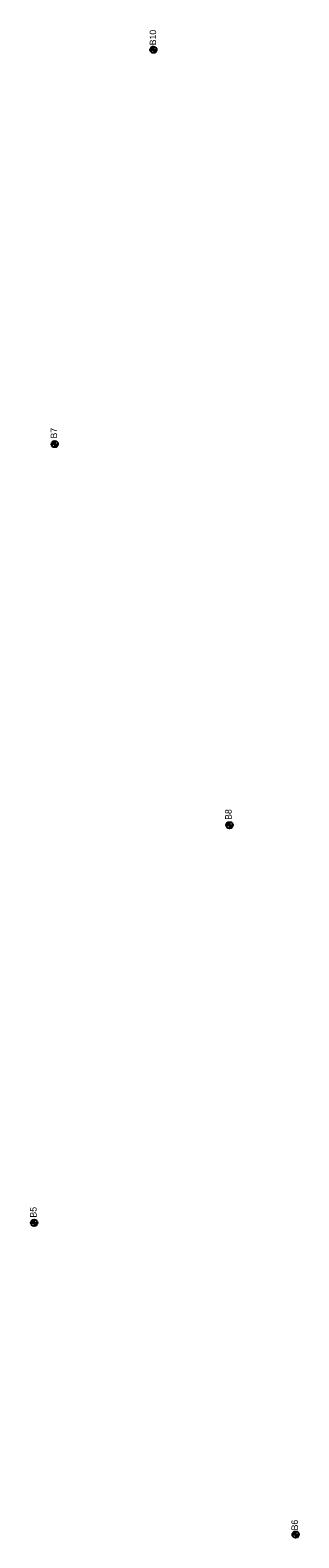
# Model space of a CAD drawing. Extents: x 327762 to 372792, y 127949 to 259367.
# Drawn here: x 361394 to 361809, y 130316 to 132638 of the extents above; entities that cross this region are included whole.
import ezdxf

# ---------------------------------------------------------------- set-up
doc = ezdxf.new("R2010")
doc.units = 0
for name, color, linetype in [('E_SOIL_BORE1 [KAPUR_CADDS_LEVELS]', 7, 'Continuous'), ('E_SOIL_BORE2 [KAPUR_CADDS_LEVELS]', 7, 'Continuous'), ('P_MARK', 7, 'Continuous')]:
    doc.layers.add(name, color=color, linetype=linetype)

msp = doc.modelspace()

# ---------------------------------------------------------------- linework, layer by layer
at = {"layer": 'P_MARK'}
for p, q in [((361584.5, 132612.5), (361584.5, 132602.5)), ((361579.5, 132607.5), (361589.5, 132607.5)), ((361427.2, 132000.1), (361437.2, 132000.1)), ((361432.2, 132005.1), (361432.2, 131995.1)), ((361697, 131413), (361707, 131413)), ((361702, 131418), (361702, 131408)), ((361395.5, 130800.6), (361405.5, 130800.6)), ((361400.5, 130805.6), (361400.5, 130795.6)), ((361799, 130320.5), (361809, 130320.5)), ((361804, 130325.5), (361804, 130315.5))]:
    msp.add_line(p, q, dxfattribs=at)
for centre in [(361584.5, 132607.5), (361432.2, 132000.1), (361702, 131413), (361400.5, 130800.6), (361804, 130320.5)]:
    msp.add_circle(centre, 5, dxfattribs=at)
for centre, radius, start, end in [((361584.5, 132607.5), 4.5, 89.9869, 179.9869), ((361584.5, 132607.5), 4, 89.9869, 179.9869), ((361584.5, 132607.5), 3.5, 89.9869, 179.9869), ((361584.5, 132607.5), 3, 89.9869, 179.9869), ((361584.5, 132607.5), 2.5, 89.9869, 179.9869), ((361584.5, 132607.5), 2, 89.9869, 179.9869), ((361584.5, 132607.5), 1.5, 89.9869, 179.9869), ((361584.5, 132607.5), 1, 89.9869, 179.9869), ((361584.5, 132607.5), 0.5, 89.9869, 179.9869), ((361584.5, 132607.5), 4.5, 269.9869, 359.9869), ((361584.5, 132607.5), 4, 269.9869, 359.9869), ((361584.5, 132607.5), 3.5, 269.9869, 359.9869), ((361584.5, 132607.5), 3, 269.9869, 359.9869), ((361584.5, 132607.5), 2.5, 269.9869, 359.9869), ((361584.5, 132607.5), 2, 269.9869, 359.9869), ((361584.5, 132607.5), 1.5, 269.9869, 359.9869), ((361584.5, 132607.5), 1, 269.9869, 359.9869), ((361584.5, 132607.5), 0.5, 269.9869, 359.9869), ((361432.2, 132000.1), 4.5, 89.9869, 179.9869), ((361432.2, 132000.1), 4, 89.9869, 179.9869), ((361432.2, 132000.1), 3.5, 89.9869, 179.9869), ((361432.2, 132000.1), 3, 89.9869, 179.9869), ((361432.2, 132000.1), 2.5, 89.9869, 179.9869), ((361432.2, 132000.1), 2, 89.9869, 179.9869), ((361432.2, 132000.1), 1.5, 89.9869, 179.9869), ((361432.2, 132000.1), 1, 89.9869, 179.9869), ((361432.2, 132000.1), 0.5, 89.9869, 179.9869), ((361432.2, 132000.1), 4.5, 269.9869, 359.9869), ((361432.2, 132000.1), 4, 269.9869, 359.9869), ((361432.2, 132000.1), 3.5, 269.9869, 359.9869), ((361432.2, 132000.1), 3, 269.9869, 359.9869), ((361432.2, 132000.1), 2.5, 269.9869, 359.9869), ((361432.2, 132000.1), 2, 269.9869, 359.9869), ((361432.2, 132000.1), 1.5, 269.9869, 359.9869), ((361432.2, 132000.1), 1, 269.9869, 359.9869), ((361432.2, 132000.1), 0.5, 269.9869, 359.9869), ((361702, 131413), 4.5, 89.9869, 179.9869), ((361702, 131413), 4, 89.9869, 179.9869), ((361702, 131413), 3.5, 89.9869, 179.9869), ((361702, 131413), 3, 89.9869, 179.9869), ((361702, 131413), 2.5, 89.9869, 179.9869), ((361702, 131413), 2, 89.9869, 179.9869), ((361702, 131413), 1.5, 89.9869, 179.9869), ((361702, 131413), 1, 89.9869, 179.9869), ((361702, 131413), 0.5, 89.9869, 179.9869), ((361702, 131413), 4.5, 269.9869, 359.9869), ((361702, 131413), 4, 269.9869, 359.9869), ((361702, 131413), 3.5, 269.9869, 359.9869), ((361702, 131413), 3, 269.9869, 359.9869), ((361702, 131413), 2.5, 269.9869, 359.9869), ((361702, 131413), 2, 269.9869, 359.9869), ((361702, 131413), 1.5, 269.9869, 359.9869), ((361702, 131413), 1, 269.9869, 359.9869), ((361702, 131413), 0.5, 269.9869, 359.9869), ((361400.5, 130800.6), 4.5, 89.9869, 179.9869), ((361400.5, 130800.6), 4, 89.9869, 179.9869), ((361400.5, 130800.6), 3.5, 89.9869, 179.9869), ((361400.5, 130800.6), 3, 89.9869, 179.9869), ((361400.5, 130800.6), 2.5, 89.9869, 179.9869), ((361400.5, 130800.6), 2, 89.9869, 179.9869), ((361400.5, 130800.6), 1.5, 89.9869, 179.9869), ((361400.5, 130800.6), 1, 89.9869, 179.9869), ((361400.5, 130800.6), 0.5, 89.9869, 179.9869), ((361400.5, 130800.6), 4.5, 269.9869, 359.9869), ((361400.5, 130800.6), 4, 269.9869, 359.9869), ((361400.5, 130800.6), 3.5, 269.9869, 359.9869), ((361400.5, 130800.6), 3, 269.9869, 359.9869), ((361400.5, 130800.6), 2.5, 269.9869, 359.9869), ((361400.5, 130800.6), 2, 269.9869, 359.9869), ((361400.5, 130800.6), 1.5, 269.9869, 359.9869), ((361400.5, 130800.6), 1, 269.9869, 359.9869), ((361400.5, 130800.6), 0.5, 269.9869, 359.9869), ((361804, 130320.5), 4.5, 89.9869, 179.9869), ((361804, 130320.5), 4, 89.9869, 179.9869), ((361804, 130320.5), 3.5, 89.9869, 179.9869), ((361804, 130320.5), 3, 89.9869, 179.9869), ((361804, 130320.5), 2.5, 89.9869, 179.9869), ((361804, 130320.5), 2, 89.9869, 179.9869), ((361804, 130320.5), 1.5, 89.9869, 179.9869), ((361804, 130320.5), 1, 89.9869, 179.9869), ((361804, 130320.5), 0.5, 89.9869, 179.9869), ((361804, 130320.5), 4.5, 269.9869, 359.9869), ((361804, 130320.5), 4, 269.9869, 359.9869), ((361804, 130320.5), 3.5, 269.9869, 359.9869), ((361804, 130320.5), 3, 269.9869, 359.9869), ((361804, 130320.5), 2.5, 269.9869, 359.9869), ((361804, 130320.5), 2, 269.9869, 359.9869), ((361804, 130320.5), 1.5, 269.9869, 359.9869), ((361804, 130320.5), 1, 269.9869, 359.9869), ((361804, 130320.5), 0.5, 269.9869, 359.9869)]:
    msp.add_arc(centre, radius, start, end, dxfattribs=at)

# ---------------------------------------------------------------- texts
at = {"layer": 'E_SOIL_BORE1 [KAPUR_CADDS_LEVELS]'}
for s, p in [('B10', (361588.7, 132614.3)), ('B7', (361435.9, 132008.7)), ('B8', (361705.2, 131421.4))]:
    msp.add_text(s, height=10, rotation=89.9869, dxfattribs=at).set_placement(p)
at = {"layer": 'E_SOIL_BORE2 [KAPUR_CADDS_LEVELS]'}
for s, p in [('B5', (361404.2, 130808.8)), ('B6', (361807.5, 130327))]:
    msp.add_text(s, height=10, rotation=89.9869, dxfattribs=at).set_placement(p)

doc.saveas('drawing.dxf')
